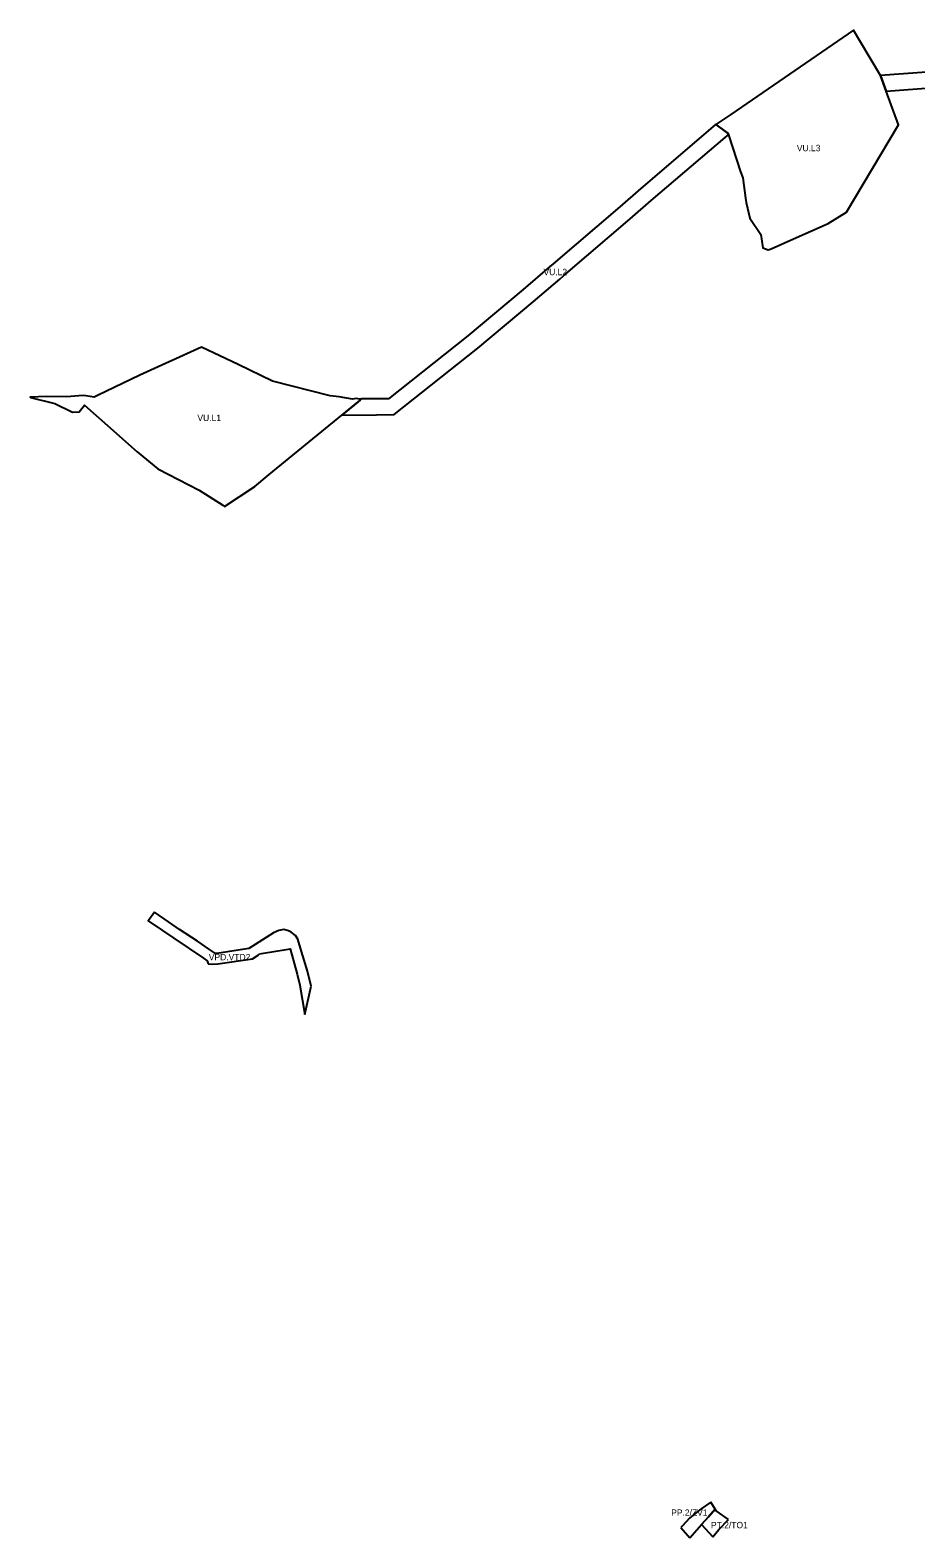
# Model space of a CAD drawing. Extents: x -439083 to -433688, y -1130252 to -1121189.
# Drawn here: x -439083 to -437411, y -1124084 to -1121237 of the extents above; entities that cross this region are included whole.
import ezdxf

# ---------------------------------------------------------------- set-up
doc = ezdxf.new("R2010")
doc.units = 0
for name, color, linetype in [('Vrstva 10', 7, 'Continuous'), ('Vrstva 13', 7, 'Continuous'), ('Vrstva 15', 7, 'Continuous'), ('Vrstva 16', 7, 'Continuous'), ('Vrstva 19', 7, 'Continuous'), ('Vrstva 22', 7, 'Continuous'), ('Vrstva 28', 7, 'Continuous'), ('Vrstva 31', 7, 'Continuous')]:
    doc.layers.add(name, color=color, linetype=linetype)

msp = doc.modelspace()

# ---------------------------------------------------------------- linework, layer by layer
at = {"layer": 'Vrstva 10'}
for p, q in [((-438848.4, -1122902.5), (-438858, -1122915.2)), ((-438821.9, -1122920.6), (-438848.4, -1122902.5)), ((-438801, -1122934.8), (-438821.9, -1122920.6)), ((-438812.2, -1122951.3), (-438755.6, -1122989.3)), ((-438767.4, -1122957.3), (-438801, -1122934.8)), ((-438744.4, -1122972.7), (-438767.4, -1122957.3)), ((-438733.3, -1122980.2), (-438744.4, -1122972.7)), ((-438649.9, -1122980.8), (-438615.6, -1122975.1)), ((-438615.6, -1122975.1), (-438607.6, -1122973.8)), ((-438564.6, -1123095.7), (-438552.8, -1123042.1))]:
    msp.add_line(p, q, dxfattribs=at)
for points in [[(-438858, -1122915.2), (-438860.5, -1122918.5), (-438833.1, -1122937.1), (-438812.2, -1122951.3)], [(-438617.9, -1122938.5), (-438623.5, -1122941.1), (-438665, -1122967.7), (-438670.4, -1122970.9), (-438730.8, -1122980.1), (-438733.3, -1122980.2)], [(-438604.2, -1122935.1), (-438604.5, -1122935), (-438613.9, -1122936.6), (-438617.9, -1122938.5)], [(-438552.8, -1123042.1), (-438559.7, -1123013.9), (-438572.5, -1122970), (-438578, -1122953.3), (-438582.4, -1122946.5), (-438590.2, -1122939.9), (-438595.4, -1122937.3), (-438604.2, -1122935.1)], [(-438652.6, -1122983.6), (-438650.7, -1122981.7), (-438649.9, -1122980.8)], [(-438607.6, -1122973.8), (-438592.4, -1122971.4), (-438579.1, -1123019.1), (-438573.9, -1123040), (-438564.6, -1123095.7)], [(-438755.6, -1122989.3), (-438748.8, -1122993.9), (-438746.8, -1122999.6)], [(-438746.8, -1122999.6), (-438739.1, -1123000.5), (-438738.7, -1123000.5)], [(-438738.7, -1123000.5), (-438728.8, -1123000), (-438663.6, -1122990.1), (-438652.6, -1122983.6)]]:
    msp.add_lwpolyline(points, dxfattribs=at)
at = {"layer": 'Vrstva 15'}
for p, q in [((-437802.4, -1124044), (-437789.6, -1124029.7)), ((-437789.6, -1124029.7), (-437798, -1124016.3)), ((-437837.6, -1124083.5), (-437815.2, -1124058.3)), ((-437815.2, -1124058.3), (-437802.4, -1124044)), ((-437854.3, -1124064.2), (-437837.6, -1124083.5))]:
    msp.add_line(p, q, dxfattribs=at)
msp.add_lwpolyline([(-437798, -1124016.3), (-437815.9, -1124028.9), (-437824.3, -1124034.8), (-437831.1, -1124040.7), (-437838, -1124046.4), (-437851.3, -1124061), (-437854.3, -1124064.2)], dxfattribs=at)
at = {"layer": 'Vrstva 19'}
for p, q in [((-437789.6, -1124029.7), (-437802.4, -1124044)), ((-437787.9, -1124032.5), (-437789.6, -1124029.7)), ((-437764.1, -1124048.9), (-437787.9, -1124032.5)), ((-437802.4, -1124044), (-437815.2, -1124058.3)), ((-437815.2, -1124058.3), (-437793.9, -1124081.6)), ((-437782.4, -1124067.6), (-437764.1, -1124048.9)), ((-437793.9, -1124081.6), (-437782.4, -1124067.6))]:
    msp.add_line(p, q, dxfattribs=at)
at = {"layer": 'Vrstva 28'}
for p, q in [((-437477.4, -1121322.8), (-437477.4, -1121322.7)), ((-437477.4, -1121322.8), (-437466.8, -1121352.1)), ((-437770.1, -1121428.3), (-437784.8, -1121417.9)), ((-438494.7, -1121963.7), (-438464, -1121938.6)), ((-438464, -1121938.6), (-438494.7, -1121963.7)), ((-438460.3, -1121935.6), (-438464, -1121938.6))]:
    msp.add_line(p, q, dxfattribs=at)
for points in [[(-437477.4, -1121322.7), (-437514.3, -1121260.3), (-437528.3, -1121237.1), (-437760.2, -1121396.4), (-437788.4, -1121415.2), (-437770.1, -1121428.3)], [(-437764.5, -1121435), (-437741.5, -1121504.5), (-437737.6, -1121516.2), (-437732.1, -1121554.2), (-437730.9, -1121562.3), (-437724.2, -1121592), (-437703.4, -1121622.9), (-437699.4, -1121648.2), (-437689.3, -1121652.1), (-437684, -1121649.8), (-437641.5, -1121631), (-437575.9, -1121602.1), (-437541.7, -1121580.8), (-437443.5, -1121416), (-437466.8, -1121352.1), (-437477.4, -1121322.8)], [(-437338.5, -1121312.5), (-437477.2, -1121322.8), (-437477.4, -1121322.8)], [(-437466.8, -1121352.1), (-437349.8, -1121343.4)], [(-437784.8, -1121417.9), (-437788.4, -1121415.2), (-437789.4, -1121415.8), (-437929.9, -1121536.3), (-437969.7, -1121570.5), (-438095.7, -1121678.2), (-438102.6, -1121684.2), (-438152.5, -1121726.9), (-438256.5, -1121814), (-438406.4, -1121933), (-438457.7, -1121933.4), (-438460.3, -1121935.6)], [(-438494.7, -1121963.7), (-438429.3, -1121963.2), (-438395.8, -1121962.9), (-438237.6, -1121837.3), (-438133.1, -1121749.8), (-438083, -1121707), (-438076.1, -1121701), (-437950.2, -1121593.3), (-437910.3, -1121559), (-437770.9, -1121439.5), (-437767.1, -1121436.8), (-437764.5, -1121435)], [(-437764.5, -1121435), (-437765.7, -1121431.4), (-437770.1, -1121428.3)], [(-437770.1, -1121428.3), (-437765.7, -1121431.4), (-437764.5, -1121435)], [(-438457.7, -1121933.4), (-438461, -1121933.5), (-438467.1, -1121932.8), (-438474.6, -1121933.8), (-438499.6, -1121929.3), (-438516.8, -1121927.4), (-438625.6, -1121899.6), (-438690.3, -1121868.4), (-438759.8, -1121835.3), (-438876.4, -1121888.6), (-438955.8, -1121926.9), (-438960.1, -1121929), (-438962.2, -1121930), (-438981.9, -1121926.9), (-438991.1, -1121927.2), (-439013.9, -1121929.2), (-439052.8, -1121929), (-439082.4, -1121930.2), (-439083.3, -1121930.2), (-439082.5, -1121930.4), (-439036.5, -1121942), (-439003.3, -1121958.1), (-438991, -1121957.9), (-438980.4, -1121944.8), (-438937.1, -1121983.5), (-438881.3, -1122033.3), (-438842.3, -1122065.1), (-438764.1, -1122105.7), (-438719.5, -1122134), (-438716.2, -1122136.1), (-438659, -1122098.6), (-438631.8, -1122076.2), (-438494.7, -1121963.7)], [(-438464, -1121938.6), (-438460.3, -1121935.6), (-438457.7, -1121933.4)]]:
    msp.add_lwpolyline(points, dxfattribs=at)

# ---------------------------------------------------------------- texts
at = {"layer": 'Vrstva 13'}
msp.add_text('VPD.VTD2', height=12, dxfattribs=at).set_placement((-438745.9, -1122993.1))
at = {"layer": 'Vrstva 16'}
msp.add_text('PP.2/ZV1', height=12, dxfattribs=at).set_placement((-437872.7, -1124041.9))
at = {"layer": 'Vrstva 22'}
msp.add_text('PT.2/TO1', height=12, dxfattribs=at).set_placement((-437797.5, -1124065.4))
at = {"layer": 'Vrstva 31'}
for s, p in [('VU.L3', (-437635.4, -1121465.6)), ('VU.L2', (-438113.8, -1121699.7)), ('VU.L1', (-438767.4, -1121975.1))]:
    msp.add_text(s, height=12, dxfattribs=at).set_placement(p)

doc.saveas('drawing.dxf')
